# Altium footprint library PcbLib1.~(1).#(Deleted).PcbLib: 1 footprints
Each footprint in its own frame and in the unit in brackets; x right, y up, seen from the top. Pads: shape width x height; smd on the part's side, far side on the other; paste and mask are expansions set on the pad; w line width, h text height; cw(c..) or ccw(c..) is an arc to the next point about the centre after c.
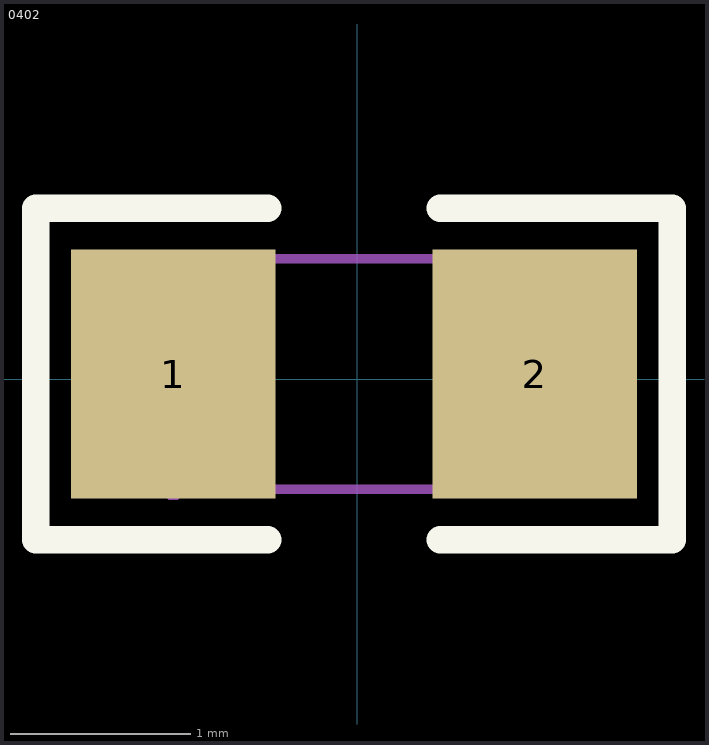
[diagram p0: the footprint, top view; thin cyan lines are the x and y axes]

## 0402 [mm]
pads (2):
  rect 1.133x1.377 smd paste-100 mask+0.051: 1(-1.017,0.028) 2(0.983,0.028)
Top Overlay:
  lines w0.152: -0.493,-0.889 -1.778,-0.889 -1.778,0.945 -0.493,0.945 ; 0.459,-0.889 1.744,-0.889 1.744,0.945 0.459,0.945
Top Paste:
  region: 0.433,-0.612 0.433,-0.192 0.878,-0.192 0.878,0.258 0.438,0.258 0.433,0.668 0.483,0.718 1.633,0.718 1.683,0.668 1.683,-0.612 1.633,-0.662 0.483,-0.662
  region: -1.717,-0.612 -1.717,0.668 -1.667,0.718 -0.517,0.718 -0.467,0.668 -0.462,0.258 -0.912,0.258 -0.912,-0.192 -0.472,-0.192 -0.467,-0.612 -0.517,-0.662 -1.667,-0.662
Mechanical 15:
  region: 0.983,-0.609 0.983,0.666 0.583,0.666 0.583,-0.609
  region: -1.017,-0.609 -1.017,0.666 -0.617,0.666 -0.617,-0.609
  region: -0.957,-0.609 -0.958,-0.585 -0.993,-0.552 -1.041,-0.552 -1.076,-0.585 -1.077,-0.609 -1.076,-0.633 -1.041,-0.667 -0.993,-0.667 -0.958,-0.633 -0.957,-0.609
  lines w0.051: -1.017,-0.609 0.983,-0.609 0.983,0.666 -1.017,0.666 -1.017,-0.609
